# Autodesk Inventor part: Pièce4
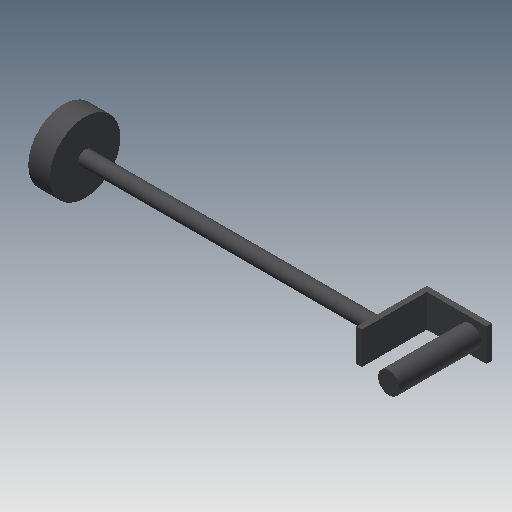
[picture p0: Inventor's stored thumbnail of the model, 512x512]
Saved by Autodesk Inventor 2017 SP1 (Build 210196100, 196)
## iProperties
Created: 2013-05
Part Number: Pièce4
Material: Générique
Document SubType Name: Modeling
Designer: jost thierry
Density: 1 g/cm^3
Mass: 1.15449 g
Surface Area: 14.0326 cm^2
Volume: 1.15449 cm^3
Appearance: Gris
Author: jost thierry
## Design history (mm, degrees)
sketch "Esquisse1"
  geometry: C1 r 2 at (101.208, -108.291) reference; 1 further point
extrude "Extrusion1" new body sketch "Esquisse1" distance "d0" = 3; taper "d2" = 0 deg; dims "d1" = 13, "d3" = 0
sketch "Esquisse2"
  geometry: L1 (-3, 3)-(9, 3); L2 (9, 3)-(9, -3); L3 (9, -3)-(-3, -3); L4 (-3, -3)-(-3, 3); C1 r 2 at (0, 0) reference; 1 further point
  constraints: 8 end point, 2 parallel, 1 horizontal, 1 perpendicular
  dimensions: "d4" = 6 distance of L3.end L1.start; "d5" = 3 distance from line of L4 C1.centre; "d6" = 12 distance of L2.end L3.end; "d7" = 3 distance from line of L3 C1.centre
extrude "Extrusion2" join sketch "Esquisse2" distance "d8" = 1; taper "d9" = 0 deg
sketch "Esquisse3"
  geometry: L1 (3, -3)-(-9, -3) reference; L2 (-9, 3)-(-8, 3); L3 (-8, 3)-(-8, -3); L4 (-8, -3)-(-9, -3); L5 (-9, -3)-(-9, 3); 1 further point
  constraints: 8 end point, 2 parallel, 1 horizontal, 1 perpendicular, 1 point on line
  dimensions: "d10" = 1 distance of L2.start L2.end
extrude "Extrusion3" join sketch "Esquisse3" distance "d11" = 12; taper "d12" = 0 deg
sketch "Esquisse4"
  geometry: L1 (0, 0)-(13, 0) reference; L2 (13, 0)-(13, 6) reference; C1 r 1.298 at (8, 3); 1 further point
  constraints: 1 centre point
  dimensions: "d14" = 3 distance from line of L1 C1.centre; "d15" = 5 distance from line of C1.centre L2
extrude "Extrusion4" join sketch "Esquisse4" distance "d16" = 55; taper "d17" = 0 deg
sketch "Esquisse5"
  geometry: C1 r 1.298 at (0, 0) reference; C2 r 6.5 at (0, 0); 1 further point
  constraints: 1 centre point, 1 coincident
  dimensions: "d18" = 13 diameter of C2
extrude "Extrusion5" join sketch "Esquisse5" distance "d19" = 4; taper "d20" = 0 deg
node "Solide1"
node "Référence1"
